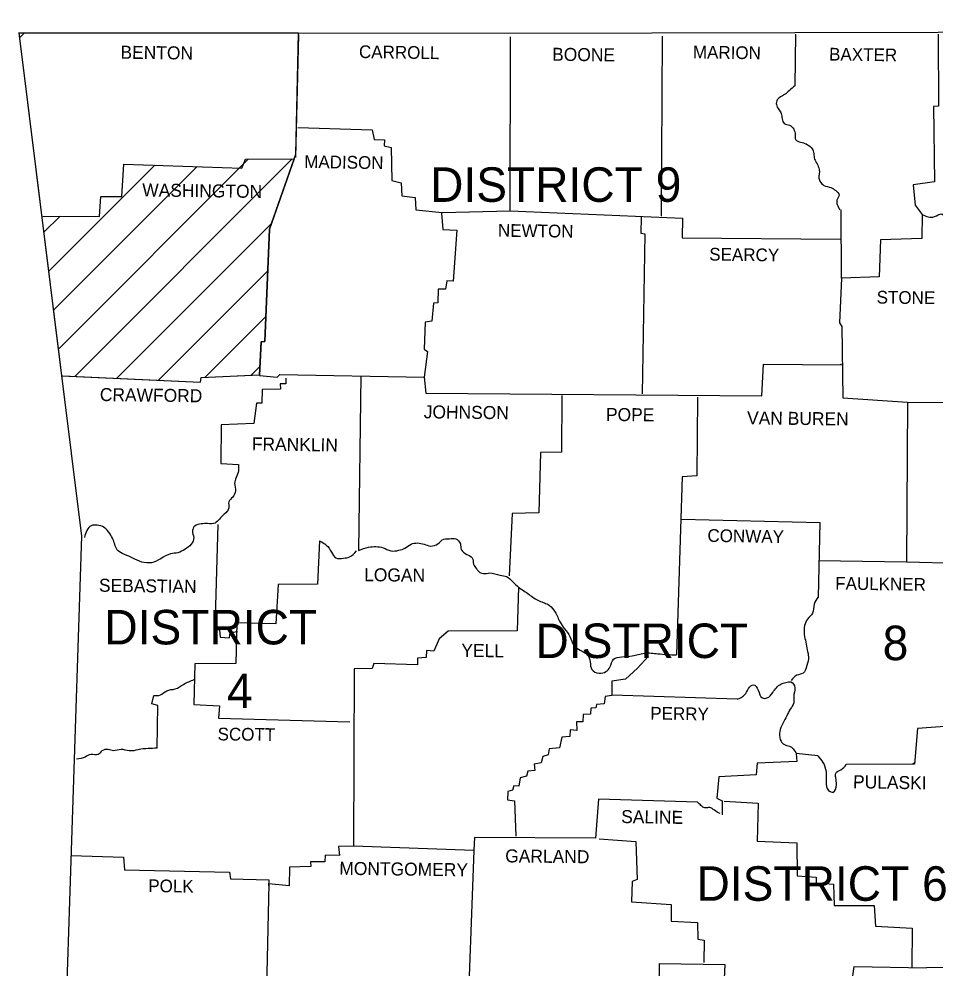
# Model space of a CAD drawing. Extents: x -17668 to 16999, y -17303 to 5867.
# Drawn here: x -17668 to -16002, y 4141 to 5867 of the extents above; entities that cross this region are included whole.
import ezdxf

# ---------------------------------------------------------------- set-up
doc = ezdxf.new("R2010")
doc.units = 0
for name, color, linetype in [('1', 7, 'Continuous'), ('2', 7, 'Continuous'), ('3', 7, 'Continuous'), ('45', 7, 'Continuous')]:
    doc.layers.add(name, color=color, linetype=linetype)

msp = doc.modelspace()

# ---------------------------------------------------------------- linework, layer by layer
at = {"layer": '1'}
for points in [[(-17667.8, 5841.4), (-16777.9, 5840.9), (-15996.9, 5842.5), (-15075.6, 5856.8), (-14648.6, 5866.7)], [(-17667.8, 5841.4), (-17553.9, 4926.7), (-17603.4, 3433.6)], [(-17159.8, 5838.1), (-17164.8, 5615.2)], [(-17160.9, 5669.7), (-17025.5, 5665.3), (-17022.2, 5647.7), (-17003.5, 5647.2), (-17004.1, 5636.1), (-16990.9, 5632.8), (-16989.8, 5572.9), (-16972.7, 5569), (-16971.6, 5545.3), (-16947.4, 5542), (-16946.3, 5520), (-16898.4, 5515.1), (-16775.1, 5517.8), (-16774, 5834.3)], [(-16498.3, 5835.4), (-16500, 5508.5)], [(-16256.1, 5839.2), (-16257.2, 5745.1)], [(-15996.9, 5839.2), (-15995.8, 5708.2), (-16005.2, 5707.7), (-16003.5, 5570.7), (-16042.1, 5565.2), (-16038.8, 5528.3), (-16025.5, 5511.2), (-16026.6, 5467.7), (-16101.5, 5465), (-16104.2, 5397.8), (-16172.5, 5395.6), (-16175.8, 5314.2), (-16171.9, 5307.6), (-16170.3, 5177.7), (-16052.5, 5170), (-16054.2, 4880), (-15960.6, 4877.2), (-15960.6, 4582.2), (-16034.4, 4576.7), (-16039.9, 4511.8), (-16163.7, 4511.2)], [(-17624.3, 5508.5), (-17521.4, 5507.9), (-17518.7, 5544.2), (-17480.7, 5544.2), (-17477.4, 5603.1), (-17262.7, 5595.4), (-17256.1, 5611.9), (-17167.5, 5612.5), (-17212.1, 5484.8), (-17220.9, 5280.6), (-17227.5, 5280.1), (-17230.8, 5218.4), (-17198.4, 5215.7), (-17193.4, 5220.6), (-16930.9, 5215.7), (-16928.1, 5186.5)], [(-16899.5, 5514), (-16897.3, 5484.3), (-16872, 5482.6), (-16878.6, 5390.1), (-16890.2, 5390.7), (-16892.4, 5375.8), (-16905.6, 5375.8), (-16906.1, 5350.5), (-16914.4, 5350), (-16917.1, 5317.5), (-16929.2, 5315.8), (-16930.9, 5266.3), (-16925.4, 5262.5), (-16930.9, 5215.7)], [(-16775.1, 5517.8), (-16461.4, 5504.6), (-16462, 5468.8), (-16174.1, 5466.6)], [(-16536.8, 5506.3), (-16537.4, 5477.6), (-16530.2, 5476), (-16534.6, 5185.4)], [(-16172.5, 5395.6), (-16173, 5519.5)], [(-16928.1, 5186.5), (-16317.2, 5181.6), (-16314.5, 5239.3), (-16172.5, 5237.7)], [(-16174.1, 5238.2), (-16172.5, 5239.9)], [(-17588, 5217.9), (-17337.6, 5206.3), (-17336.5, 5215.1), (-17231.9, 5220.1)], [(-17182.4, 5213.5), (-17182.4, 5203.6), (-17192.8, 5203.6), (-17192.3, 5193.7), (-17225.9, 5193.1), (-17226.4, 5168.3), (-17235.8, 5168.3), (-17240.7, 5131.5), (-17300.2, 5128.7), (-17300.7, 5058.8), (-17268.8, 5056.6)], [(-17046.5, 5217.9), (-17050.3, 4900.3)], [(-16681, 5182.1), (-16681.6, 5079.2), (-16719.5, 5078.6), (-16722.8, 4969.1), (-16771.3, 4967.5), (-16776.8, 4854.1)], [(-16434.5, 5179.4), (-16435.6, 5036.3), (-16462, 5034.1), (-16472.4, 4710.5)], [(-16052.5, 5170), (-15769.6, 5168.3), (-15745.4, 5179.9), (-15747.1, 4964.7), (-15763.6, 4957.6), (-15778.4, 4944.9), (-15783.4, 4940), (-15783.9, 4878.3), (-15963.9, 4878.3)], [(-16463.1, 4957.6), (-16211.6, 4951.5), (-16214.9, 4815.6)], [(-17306.2, 4947.7), (-17311.7, 4758.3), (-17303.5, 4756.1), (-17301.8, 4742.9), (-17285.3, 4741.8), (-17283.7, 4751.2), (-17270.4, 4753.4)], [(-17121.3, 4917.9), (-17125.2, 4839.2), (-17196.7, 4838.7), (-17200.6, 4767.1), (-17271.5, 4768.8), (-17273.7, 4695), (-17348, 4694.5), (-17350.2, 4620.7), (-17303.5, 4618), (-17305.1, 4595.4), (-17066.3, 4588.8)], [(-16214.3, 4882.2), (-16054.2, 4880)], [(-16759.7, 4833.7), (-16761.9, 4754.5), (-16887.4, 4753.9), (-16903.9, 4739.6), (-16913.3, 4717.6), (-16927, 4718.7), (-16927.6, 4706), (-16943.5, 4704.4), (-16943, 4692.8), (-17022.8, 4695), (-17025.5, 4686.2), (-17058.6, 4685.1), (-17059.7, 4363.2), (-17087.2, 4362.6), (-17085, 4346.1), (-17111.4, 4346.7), (-17111.9, 4334.6), (-17137.8, 4334.6), (-17137.3, 4325.8), (-17175.8, 4324.7), (-17176.3, 4291.1), (-17213.8, 4294.4), (-17219.8, 4023.6)], [(-16523.6, 4708.3), (-16543.4, 4686.8), (-16564.9, 4666.4), (-16589.7, 4662.6), (-16589.7, 4636.7), (-16601.8, 4635.1), (-16604, 4621.8), (-16617.7, 4620.7), (-16618.8, 4614.7), (-16628.2, 4614.1), (-16628.7, 4602.6), (-16641.9, 4602), (-16643, 4588.8), (-16654.1, 4588.8), (-16653.5, 4573.4), (-16665.6, 4574.5), (-16666.2, 4562.4), (-16681, 4561.3), (-16685.4, 4541.5), (-16704.1, 4539.8), (-16705.8, 4528.8), (-16715.7, 4526.1), (-16718.4, 4514.5), (-16731.1, 4511.8), (-16730, 4500.2), (-16742.7, 4499.1), (-16744.9, 4490.3), (-16756.4, 4487), (-16759.2, 4472.1), (-16768, 4472.7), (-16770.7, 4465), (-16779, 4462.2), (-16779.5, 4447.4), (-16766.9, 4445.2), (-16764.7, 4381.3)], [(-17416.8, 4540.9), (-17415.2, 4618.5), (-17426.2, 4621.8), (-17422.9, 4636.7)], [(-16362.4, 4630.1), (-16589.1, 4637.3)], [(-16215.4, 4527.2), (-16255, 4531.6), (-16253.4, 4516.7), (-16325.5, 4514), (-16327.7, 4492.5), (-16395.4, 4488.7), (-16399.2, 4450.1), (-16389.3, 4445.2), (-16389.3, 4419.9)], [(-16042.6, 4512.3), (-16039.9, 4515.1)], [(-16434.5, 4443), (-16614.4, 4448.5), (-16619.4, 4377.5), (-16839.5, 4378.6), (-16840.6, 4354.9)], [(-16385.5, 4444.6), (-16323.8, 4440.8), (-16326, 4372), (-16253.9, 4369.2), (-16252.8, 4309.2), (-16218.7, 4306.5), (-16218.7, 4296), (-16186.8, 4293.8), (-16185.7, 4255.3), (-16113.1, 4255.3), (-16110.9, 4217.3), (-16043.7, 4214), (-16044.3, 4142.5)], [(-16612.8, 4376.4), (-16546.2, 4371.4), (-16544, 4302.1), (-16553.3, 4298.8), (-16554.4, 4261.9), (-16482.3, 4257), (-16482.3, 4226.7), (-16434.5, 4223.9), (-16433.9, 4193.7), (-16422.4, 4192), (-16422.9, 4151.3)], [(-16840.6, 4354.9), (-17059.7, 4363.2)], [(-16840.6, 4354.9), (-16853.3, 4012.1)], [(-17573.1, 4346.1), (-17477.9, 4342.8), (-17475.7, 4319.7), (-17285.3, 4315.8), (-17283.1, 4303.7), (-17213.8, 4301.5), (-17214.3, 4291.1)], [(-15387.7, 4205.8), (-15595.7, 4211.3), (-15596.8, 4143.6), (-16017.8, 4141.9)], [(-16849.4, 4057.7), (-16534.6, 4053.3), (-16528.6, 4105.6), (-16503.8, 4105.6), (-16503.3, 4149.6), (-16384.4, 4148), (-16385.5, 4121.6), (-16354.7, 4119.4), (-16354.7, 4070.9), (-16334.8, 4069.3)], [(-16334.8, 4069.3), (-16304, 4073.7), (-16301.8, 4092.4), (-16283.7, 4095.7), (-16282.6, 4106.7), (-16154.3, 4110.6), (-16149.4, 4144.1), (-16017.8, 4141.9)]]:
    msp.add_lwpolyline(points, dxfattribs=at)
for points in [[(-16257.2, 5745.1), (-16267.2, 5736.9), (-16276, 5729.2), (-16289.2, 5719.8), (-16290.8, 5711), (-16286.4, 5702.2), (-16282, 5695), (-16280.4, 5685.1), (-16276.5, 5676.9), (-16267.2, 5673.6), (-16259.4, 5666.4), (-16256.7, 5656.5), (-16255.6, 5647.2), (-16246.8, 5642.8), (-16236.9, 5639.5), (-16227.5, 5632.8), (-16223.1, 5624.6), (-16222, 5614.1), (-16218.2, 5605.9), (-16213.8, 5596), (-16212.7, 5587.7), (-16213.8, 5579.5), (-16211.6, 5571.8), (-16204.4, 5564.1), (-16191.8, 5560.2), (-16182.9, 5554.7), (-16176.9, 5547), (-16180.7, 5537.6), (-16180.2, 5529.4), (-16175.2, 5519.5)], [(-16025.5, 5511.2), (-16003.5, 5507.4), (-15990.3, 5512.3), (-15981, 5498), (-15976, 5487), (-15967.8, 5471), (-15954.6, 5466.1), (-15944.6, 5457.3), (-15944.6, 5447.9), (-15953.4, 5439.1), (-15960.1, 5430.3), (-15957.9, 5419.9), (-15955.7, 5405.5), (-15955.7, 5391.8), (-15959, 5379.1), (-15961.7, 5367.6), (-15959, 5357.7), (-15948.5, 5359.3), (-15937.5, 5367.6), (-15925.9, 5367.6), (-15914.9, 5361.5), (-15903.4, 5351.1), (-15891.8, 5353.3), (-15882.5, 5356), (-15869.2, 5359.9), (-15859.9, 5354.9), (-15851.6, 5348.3), (-15841.7, 5337.9), (-15832.4, 5331.3), (-15820.3, 5325.2), (-15805.4, 5321.3), (-15791.6, 5312), (-15789.4, 5296), (-15790, 5282.3), (-15791.1, 5265.2), (-15792.2, 5246.5), (-15790.5, 5228.3), (-15784.5, 5216.2), (-15776.8, 5201.9), (-15774.6, 5188.7), (-15775.1, 5167.8)], [(-17268.8, 5056.6), (-17268.8, 5045.1), (-17273.2, 5033), (-17275.9, 5022.5), (-17274.3, 5008.7), (-17279.3, 4997.7), (-17286.4, 4988.9), (-17286.4, 4977.9), (-17294.7, 4966.4), (-17303.5, 4957.6), (-17311.2, 4950.4), (-17324.9, 4949.3), (-17336.5, 4948.8), (-17348, 4944.9), (-17352.4, 4936.6), (-17350.2, 4924), (-17354.7, 4911.9), (-17366.2, 4902.5), (-17378.9, 4896.5), (-17392.1, 4894.3), (-17410.2, 4885.5), (-17426.7, 4878.3), (-17444.4, 4879.4), (-17460.9, 4886.6), (-17475.7, 4893.2), (-17487.3, 4899.8), (-17496.6, 4920.1), (-17502.7, 4931.1), (-17513.2, 4942.2), (-17525.8, 4946.6), (-17536.3, 4945.5), (-17548.9, 4924)], [(-17121.3, 4917.9), (-17109.2, 4910.2), (-17099.8, 4897.6), (-17091.6, 4887.1), (-17077.8, 4886.6), (-17066.8, 4888.8), (-17054.2, 4899.8)], [(-17050.3, 4900.3), (-17032.1, 4906.4), (-17018.9, 4907.5), (-17005.7, 4905.3), (-16992, 4899.8), (-16977.1, 4900.9), (-16966.1, 4904.7), (-16955.1, 4911.9), (-16943, 4914.1), (-16931.4, 4911.9), (-16919.3, 4908.6), (-16906.1, 4912.4), (-16898.4, 4919.6), (-16885.2, 4921.8), (-16873.6, 4921.8), (-16865.4, 4912.4), (-16863.7, 4902.5), (-16853.3, 4893.2), (-16843.9, 4887.1), (-16841.2, 4875.6), (-16836.2, 4867.3), (-16831.3, 4861.8), (-16824.1, 4858.5), (-16812, 4859.6), (-16793.3, 4855.7), (-16781.2, 4853), (-16770.2, 4843.6), (-16759.7, 4833.7)], [(-16759.7, 4833.7), (-16740.5, 4820.5), (-16722.3, 4809), (-16703.6, 4800.7), (-16693.1, 4788.6), (-16683.8, 4769.9), (-16676.1, 4758.3), (-16666.2, 4744), (-16659, 4728.1), (-16647.4, 4719.3), (-16635.3, 4711.6), (-16629.3, 4697.8), (-16626.5, 4684), (-16613.3, 4677.4), (-16600.7, 4680.2), (-16593.5, 4688.4), (-16586.9, 4702.7), (-16572, 4707.2), (-16552.8, 4708.8), (-16530.8, 4713.8), (-16506.6, 4712.7), (-16472.4, 4710.5)], [(-16214.9, 4815.6), (-16222, 4802.9), (-16225.3, 4786.4), (-16234.1, 4775.9), (-16239.6, 4763.8), (-16240.2, 4747.9), (-16237.4, 4733.6), (-16234.7, 4719.8), (-16232.5, 4707.2), (-16235.2, 4691.2), (-16242.4, 4677.4), (-16253.4, 4673.6), (-16263.8, 4664.2)], [(-17422.9, 4636.7), (-17410.8, 4637.8), (-17399.2, 4645.5), (-17383.8, 4648.8), (-17368.4, 4657.1), (-17349.1, 4665.9)], [(-16362.4, 4630.1), (-16348.6, 4637.8), (-16341.4, 4649.4), (-16332.6, 4656.5), (-16323.8, 4646.6), (-16316.1, 4632.3), (-16307.9, 4632.3), (-16297.4, 4642.2), (-16290.8, 4651), (-16282.6, 4657.6), (-16273.8, 4660.4), (-16264.4, 4661.5), (-16257.2, 4651), (-16259.4, 4634.5), (-16259.4, 4623.5), (-16265.5, 4611.9), (-16272.1, 4599.8), (-16279.3, 4586.1), (-16284.8, 4571.2), (-16283.7, 4556.9), (-16276, 4547.5), (-16267.2, 4544.8), (-16255, 4532.7)], [(-17416.8, 4540.9), (-17432.8, 4540.4), (-17451, 4538.2), (-17467.5, 4536), (-17482.3, 4538.7), (-17496.1, 4536.5), (-17505.4, 4538.7), (-17517, 4536), (-17523.6, 4529.4), (-17537.4, 4529.4), (-17547.3, 4525), (-17563.2, 4521.1)], [(-16215.4, 4527.2), (-16206.1, 4515.1), (-16200.6, 4498.6), (-16200.6, 4479.9), (-16196.2, 4464.4), (-16187.4, 4461.1), (-16181.8, 4474.4), (-16182.9, 4487.6), (-16182.9, 4495.3), (-16173.6, 4501.9), (-16163.7, 4511.2)], [(-16393.2, 4422.6), (-16403.6, 4428.1), (-16411.9, 4433.1), (-16420.7, 4432.5), (-16427.9, 4436.9), (-16434.5, 4443)]]:
    msp.add_spline(points, degree=3, dxfattribs=at)
at = {"layer": '45'}
for p, q in [((-17666.7, 5832.6), (-17657.9, 5841.4)), ((-17596.2, 5266.7), (-17250.9, 5612)), ((-17566.5, 5216.9), (-17170.9, 5612.5)), ((-17613.8, 5408.2), (-17420.9, 5601.1)), ((-17605, 5337.4), (-17344.1, 5598.3)), ((-17622.6, 5478.9), (-17593.2, 5508.3)), ((-17490.4, 5213.4), (-17208.4, 5495.4)), ((-17414.4, 5209.9), (-17215.4, 5408.9)), ((-17329.2, 5215.5), (-17219, 5325.7)), ((-17245.7, 5219.4), (-17229.9, 5235.2)), ((-17338.3, 5206.4), (-17337.5, 5207.2))]:
    msp.add_line(p, q, dxfattribs=at)
msp.add_lwpolyline([(-17159.8, 5841.1), (-17667.8, 5841.4), (-17590.2, 5218), (-17337.6, 5206.3), (-17336.5, 5215.1), (-17230.7, 5220.1), (-17227.5, 5280.1), (-17220.9, 5280.6), (-17212.1, 5484.8), (-17164.7, 5620.7), (-17159.8, 5841.1)], dxfattribs=at)

# ---------------------------------------------------------------- texts
at = {"layer": '2'}
for s, height, rotation, p in [('BENTON', 23.67, 359.2527, (-17483.4, 5794.6)), ('CARROLL', 23.11, 359.1481, (-17049.8, 5795.8)), ('BOONE', 23.67, 359.4001, (-16698.6, 5790.8)), ('MARION', 23.11, 359.1854, (-16442.7, 5795.2)), ('BAXTER', 23.11, 359.2559, (-16195.1, 5791.3)), ('MADISON', 23.11, 359.0906, (-17149.4, 5596)), ('WASHINGTON', 23.66, 359.232, (-17443.8, 5544.2)), ('NEWTON', 23.11, 359.2717, (-16797.1, 5471)), ('SEARCY', 23.11, 359.2527, (-16413, 5427.6)), ('STONE', 23.11, 359.4001, (-16108.6, 5349.4)), ('CRAWFORD', 23.66, 359.2771, (-17520.9, 5172.2)), ('JOHNSON', 23.67, 359.3514, (-16932, 5140.8)), ('POPE', 23.67, 359.6155, (-16600.7, 5135.9)), ('VAN BUREN', 23.67, 359.3508, (-16344.2, 5129.8)), ('FRANKLIN', 23.67, 359.1815, (-17244.6, 5082.5)), ('CONWAY', 23.11, 359.0371, (-16416.3, 4916.3)), ('LOGAN', 23.67, 359.3969, (-17040.4, 4844.7)), ('SEBASTIAN', 23.66, 359.2816, (-17522.5, 4825.5)), ('FAULKNER', 23.11, 359.2486, (-16184, 4829.3)), ('YELL', 23.67, 359.1987, (-16863.7, 4707.2)), ('PERRY', 23.11, 359.0858, (-16520.3, 4593.2)), ('SCOTT', 23.11, 359.4063, (-17306.8, 4555.3)), ('PULASKI', 23.67, 359.053, (-16151.6, 4468.3)), ('SALINE', 23.67, 359.1491, (-16573.1, 4405)), ('GARLAND', 23.67, 359.3658, (-16783.9, 4333.5)), ('MONTGOMERY', 23.67, 359.2944, (-17085.5, 4310.9)), ('POLK', 23.11, 359.2152, (-17432.8, 4279.5))]:
    msp.add_text(s, height=height, rotation=rotation, dxfattribs=at).set_placement(p)
at = {"layer": '3'}
for s, height, p in [('DISTRICT 9', 62.74, (-16920.4, 5534.3)), ('DISTRICT', 62.74, (-17512.6, 4729.7)), ('DISTRICT', 62.74, (-16728.9, 4704.9)), ('8', 62.7, (-16097.6, 4701.1)), ('4', 62.7, (-17289.7, 4614.1)), ('DISTRICT 6', 62.74, (-16436.1, 4263.6))]:
    msp.add_text(s, height=height, dxfattribs=at).set_placement(p)

doc.saveas('drawing.dxf')
